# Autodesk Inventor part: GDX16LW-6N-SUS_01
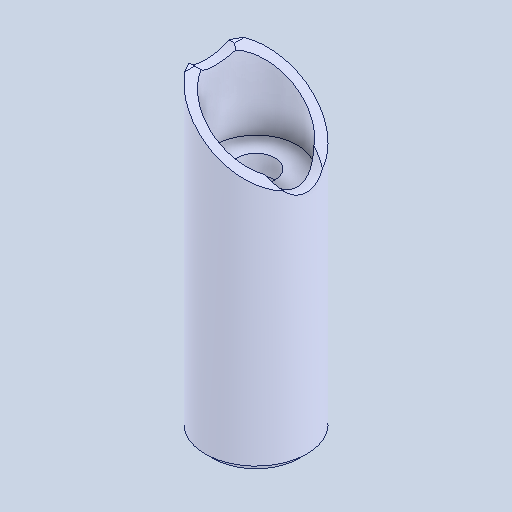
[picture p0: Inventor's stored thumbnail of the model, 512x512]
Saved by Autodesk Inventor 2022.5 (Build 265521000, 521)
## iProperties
Created: 2024-06
Part Number: GDX16LW-6N-SUS_01
Material: 一般
Document SubType Name: Modeling
Designer: ImaoCorp
Density: 1 g/cm^3
Appearance: 既定
Author: ImaoCorp
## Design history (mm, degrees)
feature "GDX16LW-6N-SUS_01"
node "ソリッド1"
